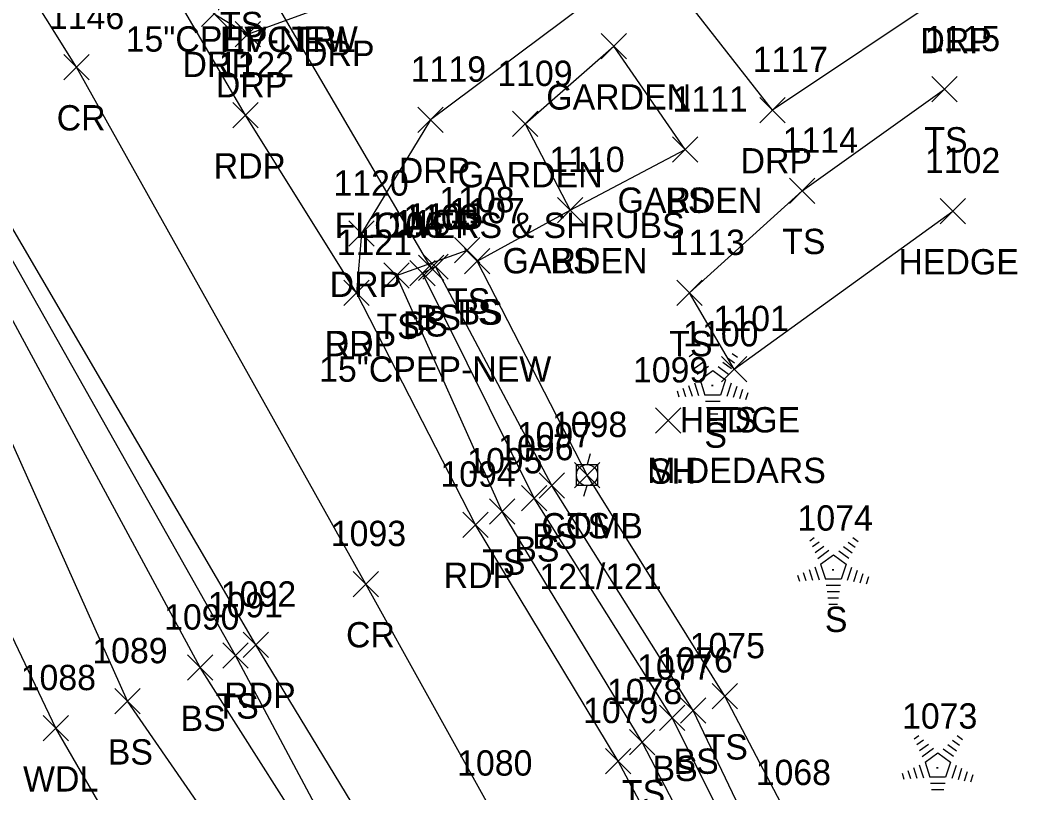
# Model space of a CAD drawing. Extents: x 1501299 to 1502485, y 381423 to 383765.
# Drawn here: x 1501851.9 to 1501931.5, y 382883 to 382944 of the extents above; entities that cross this region are included whole.
import ezdxf

# ---------------------------------------------------------------- set-up
doc = ezdxf.new("R2010")
doc.units = 0
for name, color, linetype in [('C_A', 7, 'Continuous'), ('D_A', 7, 'Continuous'), ('D_C', 7, 'Continuous'), ('D_I', 7, 'Continuous'), ('D_TIC', 7, 'Continuous'), ('DCP', 7, 'Continuous'), ('L_A', 7, 'Continuous'), ('L_C', 7, 'Continuous'), ('L_I', 7, 'Continuous'), ('L_TIC', 7, 'Continuous'), ('LAHR', 7, 'Continuous'), ('LAPB', 7, 'Continuous'), ('LAWA', 7, 'Continuous'), ('LELB', 7, 'Continuous'), ('LTC', 7, 'Continuous'), ('P_A', 7, 'Continuous'), ('P_I', 7, 'Continuous'), ('P_TIC', 7, 'Continuous'), ('PET', 7, 'Continuous'), ('PRC', 7, 'Continuous'), ('R_A', 7, 'Continuous'), ('R_I', 7, 'Continuous'), ('R_TIC', 7, 'Continuous'), ('RDP', 7, 'Continuous'), ('U_A', 7, 'Continuous'), ('U_C', 7, 'Continuous'), ('U_I', 7, 'Continuous'), ('UP', 7, 'Continuous')]:
    doc.layers.add(name, color=color, linetype=linetype)

msp = doc.modelspace()

# ---------------------------------------------------------------- linework, layer by layer
at = {"layer": 'D_TIC'}
for points in [[(1501883.401, 382923.481), (1501885.401, 382925.481)], [(1501885.401, 382923.481), (1501883.401, 382925.481)]]:
    msp.add_lwpolyline(points, dxfattribs=at)
at = {"layer": 'DCP'}
msp.add_lwpolyline([(1501884.401, 382924.481), (1501869.119, 382950.545)], dxfattribs=at)
at = {"layer": 'L_TIC'}
for points in [[(1501897.823, 382940.969), (1501899.823, 382942.969)], [(1501899.823, 382940.969), (1501897.823, 382942.969)], [(1501897.823, 382940.969), (1501899.823, 382942.969)], [(1501899.823, 382940.969), (1501897.823, 382942.969)], [(1501923.945, 382937.582), (1501925.945, 382939.582)], [(1501925.945, 382937.582), (1501923.945, 382939.582)], [(1501890.835, 382934.833), (1501892.835, 382936.833)], [(1501892.835, 382934.833), (1501890.835, 382936.833)], [(1501890.835, 382934.833), (1501892.835, 382936.833)], [(1501892.835, 382934.833), (1501890.835, 382936.833)], [(1501903.45, 382932.816), (1501905.45, 382934.816)], [(1501905.45, 382932.816), (1501903.45, 382934.816)], [(1501903.45, 382932.816), (1501905.45, 382934.816)], [(1501905.45, 382932.816), (1501903.45, 382934.816)], [(1501912.716, 382929.558), (1501914.716, 382931.558)], [(1501914.716, 382929.558), (1501912.716, 382931.558)], [(1501894.375, 382928.039), (1501896.375, 382930.039)], [(1501896.375, 382928.039), (1501894.375, 382930.039)], [(1501894.375, 382928.039), (1501896.375, 382930.039)], [(1501896.375, 382928.039), (1501894.375, 382930.039)], [(1501924.605, 382927.951), (1501926.605, 382929.951)], [(1501926.605, 382927.951), (1501924.605, 382929.951)], [(1501886.244, 382924.863), (1501888.244, 382926.863)], [(1501888.244, 382924.863), (1501886.244, 382926.863)], [(1501886.244, 382924.863), (1501888.244, 382926.863)], [(1501888.244, 382924.863), (1501886.244, 382926.863)], [(1501883.747, 382923.568), (1501885.747, 382925.568)], [(1501885.747, 382923.568), (1501883.747, 382925.568)], [(1501883.747, 382923.568), (1501885.747, 382925.568)], [(1501885.747, 382923.568), (1501883.747, 382925.568)], [(1501887.043, 382923.994), (1501889.043, 382925.994)], [(1501889.043, 382923.994), (1501887.043, 382925.994)], [(1501887.043, 382923.994), (1501889.043, 382925.994)], [(1501889.043, 382923.994), (1501887.043, 382925.994)], [(1501880.668, 382922.868), (1501882.668, 382924.868)], [(1501882.668, 382922.868), (1501880.668, 382924.868)], [(1501882.724, 382923.051), (1501884.724, 382925.051)], [(1501884.724, 382923.051), (1501882.724, 382925.051)], [(1501903.796, 382921.494), (1501905.796, 382923.494)], [(1501905.796, 382921.494), (1501903.796, 382923.494)], [(1501907.338, 382915.478), (1501909.338, 382917.478)], [(1501909.338, 382915.478), (1501907.338, 382917.478)], [(1501907.338, 382915.478), (1501909.338, 382917.478)], [(1501909.338, 382915.478), (1501907.338, 382917.478)], [(1501902.117, 382911.426), (1501904.117, 382913.426)], [(1501904.117, 382911.426), (1501902.117, 382913.426)], [(1501895.712, 382907.113), (1501897.712, 382909.113)], [(1501897.712, 382907.113), (1501895.712, 382909.113)], [(1501892.938, 382906.292), (1501894.938, 382908.292)], [(1501894.938, 382906.292), (1501892.938, 382908.292)], [(1501891.525, 382905.285), (1501893.525, 382907.285)], [(1501893.525, 382905.285), (1501891.525, 382907.285)], [(1501889.021, 382904.247), (1501891.021, 382906.247)], [(1501891.021, 382904.247), (1501889.021, 382906.247)], [(1501867.959, 382892.881), (1501869.959, 382894.881)], [(1501869.959, 382892.881), (1501867.959, 382894.881)], [(1501865.166, 382891.912), (1501867.166, 382893.912)], [(1501867.166, 382891.912), (1501865.166, 382893.912)], [(1501859.416, 382889.256), (1501861.416, 382891.256)], [(1501861.416, 382889.256), (1501859.416, 382891.256)], [(1501906.588, 382889.652), (1501908.588, 382891.652)], [(1501908.588, 382889.652), (1501906.588, 382891.652)], [(1501904.102, 382888.525), (1501906.102, 382890.525)], [(1501906.102, 382888.525), (1501904.102, 382890.525)], [(1501902.441, 382887.957), (1501904.441, 382889.957)], [(1501904.441, 382887.957), (1501902.441, 382889.957)], [(1501853.75, 382887.13), (1501855.75, 382889.13)], [(1501855.75, 382887.13), (1501853.75, 382889.13)], [(1501900.055, 382886.028), (1501902.055, 382888.028)], [(1501902.055, 382886.028), (1501900.055, 382888.028)]]:
    msp.add_lwpolyline(points, dxfattribs=at)
at = {"layer": 'LAHR'}
msp.add_lwpolyline([(1501908.338, 382916.478), (1501925.605, 382928.951)], dxfattribs=at)
at = {"layer": 'LAPB'}
for points in [[(1501891.835, 382935.833), (1501895.375, 382929.039), (1501904.45, 382933.816), (1501898.823, 382941.969)], [(1501891.835, 382935.833), (1501898.823, 382941.969)]]:
    msp.add_lwpolyline(points, dxfattribs=at)
at = {"layer": 'LAWA'}
msp.add_lwpolyline([(1501942.677, 382714.841), (1501935.183, 382744.721), (1501913.337, 382785.2), (1501893.395, 382826.433), (1501865.291, 382869.925), (1501854.75, 382888.13), (1501835.928, 382927.55), (1501822.234, 382953.468), (1501796.607, 382993.044), (1501779.613, 383024.31), (1501754.165, 383064.049), (1501733.525, 383095.142)], dxfattribs=at)
at = {"layer": 'LELB'}
for points in [[(1501947.071, 382716.202), (1501936.789, 382745.616), (1501921.74, 382787.499), (1501900.168, 382829.778), (1501877.018, 382875.801), (1501866.166, 382892.912), (1501844.624, 382932.733), (1501828.058, 382959.038), (1501805.265, 382995.601), (1501783.687, 383028.162), (1501760.133, 383067.523), (1501734.806, 383103.876), (1501716.067, 383128.727), (1501702.976, 383136.285), (1501694.191, 383132.723)], [(1501947.958, 382716.119), (1501939.996, 382745.704), (1501923.414, 382788.324), (1501902.81, 382830.435), (1501868.959, 382893.881), (1501846.402, 382933.734), (1501830.033, 382960.147), (1501806.634, 382996.692), (1501785.685, 383029.202), (1501761.094, 383068.04), (1501736.237, 383105.316), (1501718.865, 383131.579)], [(1501945.344, 382716.136), (1501936.673, 382745.194), (1501918.388, 382786.659), (1501897.882, 382827.989), (1501871.615, 382874.073), (1501860.416, 382890.256), (1501841.87, 382931.652), (1501826.472, 382956.951), (1501803.66, 382993.76), (1501782.057, 383026.726), (1501758.572, 383066.643), (1501733.616, 383102.86), (1501712.412, 383124.491), (1501694.918, 383122.167), (1501687.272, 383121.659)], [(1501908.338, 382916.478), (1501904.796, 382922.494), (1501913.716, 382930.558), (1501924.945, 382938.582)], [(1501888.043, 382924.994), (1501895.375, 382929.039)], [(1501911.592, 382870.97), (1501909.37, 382871.043), (1501901.055, 382887.028), (1501890.021, 382905.247), (1501881.668, 382923.868), (1501887.244, 382925.863)], [(1501913.743, 382873.819), (1501912.85, 382880.639), (1501907.588, 382890.652), (1501896.712, 382908.113), (1501888.043, 382924.994), (1501887.244, 382925.863)], [(1501911.192, 382873.468), (1501903.441, 382888.957), (1501892.525, 382906.285), (1501883.724, 382924.051), (1501884.747, 382924.568)], [(1501911.192, 382873.468), (1501911.937, 382871.769), (1501912.981, 382872.458), (1501912.438, 382874.164), (1501905.102, 382889.525), (1501893.938, 382907.292), (1501884.747, 382924.568)]]:
    msp.add_lwpolyline(points, dxfattribs=at)
at = {"layer": 'LTC'}
for p, q in [((1501904.789, 382917.479), (1501905.143, 382917.736)), ((1501904.998, 382917.014), (1501905.528, 382917.398)), ((1501908.187, 382917.719), (1501908.606, 382917.415)), ((1501905.208, 382916.548), (1501905.912, 382917.059)), ((1501905.418, 382916.082), (1501906.296, 382916.72)), ((1501907.074, 382916.674), (1501907.883, 382916.086)), ((1501907.445, 382917.023), (1501908.124, 382916.529)), ((1501907.816, 382917.371), (1501908.366, 382916.972)), ((1501905.642, 382915.627), (1501906.654, 382916.361)), ((1501906.654, 382916.361), (1501907.651, 382915.636)), ((1501904.732, 382915.191), (1501905.003, 382914.356)), ((1501905.188, 382915.408), (1501905.518, 382914.389)), ((1501905.642, 382915.627), (1501906.029, 382914.434)), ((1501907.651, 382915.636), (1501907.26, 382914.434)), ((1501908.088, 382915.366), (1501907.751, 382914.326)), ((1501908.533, 382915.115), (1501908.246, 382914.231)), ((1501903.821, 382914.758), (1501903.973, 382914.29)), ((1501904.277, 382914.975), (1501904.488, 382914.323)), ((1501907.26, 382914.434), (1501906.029, 382914.434)), ((1501908.978, 382914.865), (1501908.741, 382914.136)), ((1501909.422, 382914.615), (1501909.235, 382914.041)), ((1501907.221, 382913.934), (1501906.077, 382913.934)), ((1501907.138, 382913.434), (1501906.149, 382913.434)), ((1501907.054, 382912.934), (1501906.222, 382912.934)), ((1501906.97, 382912.434), (1501906.295, 382912.434)), ((1501914.305, 382902.933), (1501914.659, 382903.191)), ((1501917.703, 382903.174), (1501918.122, 382902.869)), ((1501914.514, 382902.468), (1501915.044, 382902.852)), ((1501914.724, 382902.002), (1501915.428, 382902.513)), ((1501916.961, 382902.477), (1501917.64, 382901.983)), ((1501917.332, 382902.825), (1501917.882, 382902.426)), ((1501914.934, 382901.536), (1501915.812, 382902.174)), ((1501915.158, 382901.081), (1501916.17, 382901.816)), ((1501916.17, 382901.816), (1501917.167, 382901.091)), ((1501916.59, 382902.129), (1501917.399, 382901.54)), ((1501914.704, 382900.862), (1501915.034, 382899.843)), ((1501915.158, 382901.081), (1501915.545, 382899.888)), ((1501917.167, 382901.091), (1501916.776, 382899.888)), ((1501917.604, 382900.82), (1501917.267, 382899.78)), ((1501913.337, 382900.212), (1501913.489, 382899.744)), ((1501913.793, 382900.429), (1501914.004, 382899.777)), ((1501914.248, 382900.646), (1501914.519, 382899.81)), ((1501916.776, 382899.888), (1501915.545, 382899.888)), ((1501918.049, 382900.569), (1501917.762, 382899.685)), ((1501918.494, 382900.319), (1501918.257, 382899.59)), ((1501918.938, 382900.069), (1501918.751, 382899.495)), ((1501916.737, 382899.388), (1501915.593, 382899.388)), ((1501916.654, 382898.888), (1501915.665, 382898.888)), ((1501916.57, 382898.388), (1501915.738, 382898.388)), ((1501916.486, 382897.888), (1501915.811, 382897.888)), ((1501922.557, 382887.3), (1501922.911, 382887.558)), ((1501922.766, 382886.835), (1501923.295, 382887.219)), ((1501925.584, 382887.192), (1501926.133, 382886.793)), ((1501925.955, 382887.54), (1501926.374, 382887.236)), ((1501922.976, 382886.369), (1501923.679, 382886.88)), ((1501923.185, 382885.903), (1501924.064, 382886.541)), ((1501924.842, 382886.495), (1501925.651, 382885.907)), ((1501925.213, 382886.844), (1501925.892, 382886.35)), ((1501923.41, 382885.448), (1501924.422, 382886.183)), ((1501924.422, 382886.183), (1501925.419, 382885.458)), ((1501922.044, 382884.796), (1501922.256, 382884.144)), ((1501922.5, 382885.013), (1501922.771, 382884.177)), ((1501922.955, 382885.229), (1501923.286, 382884.21)), ((1501923.41, 382885.448), (1501923.797, 382884.255)), ((1501925.419, 382885.458), (1501925.027, 382884.255)), ((1501925.856, 382885.187), (1501925.518, 382884.147)), ((1501926.301, 382884.936), (1501926.013, 382884.052)), ((1501921.589, 382884.579), (1501921.741, 382884.111)), ((1501925.027, 382884.255), (1501923.797, 382884.255)), ((1501926.745, 382884.686), (1501926.508, 382883.957)), ((1501927.189, 382884.436), (1501927.003, 382883.862)), ((1501924.989, 382883.755), (1501923.844, 382883.755)), ((1501924.905, 382883.255), (1501923.917, 382883.255))]:
    msp.add_line(p, q, dxfattribs=at)
at = {"layer": 'P_TIC'}
for points in [[(1501855.391, 382939.32), (1501857.391, 382941.32)], [(1501857.391, 382939.32), (1501855.391, 382941.32)], [(1501868.738, 382935.529), (1501870.738, 382937.529)], [(1501870.738, 382935.529), (1501868.738, 382937.529)], [(1501877.505, 382921.493), (1501879.505, 382923.493)], [(1501879.505, 382921.493), (1501877.505, 382923.493)], [(1501886.899, 382903.195), (1501888.899, 382905.195)], [(1501888.899, 382903.195), (1501886.899, 382905.195)], [(1501878.244, 382898.507), (1501880.244, 382900.507)], [(1501880.244, 382898.507), (1501878.244, 382900.507)], [(1501869.565, 382893.723), (1501871.565, 382895.723)], [(1501871.565, 382893.723), (1501869.565, 382895.723)], [(1501898.175, 382884.527), (1501900.175, 382886.527)], [(1501900.175, 382884.527), (1501898.175, 382886.527)]]:
    msp.add_lwpolyline(points, dxfattribs=at)
at = {"layer": 'PET'}
for points in [[(1501949.648, 382716.507), (1501941.04, 382745.977), (1501925.012, 382788.592), (1501904.253, 382831.621), (1501880.763, 382877.887), (1501870.565, 382894.723), (1501847.406, 382934.273), (1501830.938, 382961.01), (1501807.981, 382997.987), (1501787.075, 383029.946), (1501762.257, 383068.782), (1501737.378, 383106.292), (1501722.895, 383129.668), (1501696.699, 383166.339)], [(1501971.372, 382720.654), (1501961.032, 382754.708), (1501942.926, 382798.84), (1501930.998, 382825.078), (1501924.576, 382839.599), (1501916.528, 382851.603), (1501908.311, 382868.386), (1501899.175, 382885.527), (1501887.899, 382904.195), (1501878.505, 382922.493), (1501869.738, 382936.529), (1501858.065, 382956.489), (1501847.469, 382974.349), (1501824.868, 383010.254), (1501802.294, 383043.804), (1501787.994, 383066.094), (1501768.484, 383096.751)]]:
    msp.add_lwpolyline(points, dxfattribs=at)
at = {"layer": 'PRC'}
msp.add_lwpolyline([(1501960.612, 382718.648), (1501950.96, 382750.482), (1501934.965, 382791.852), (1501913.074, 382836.935), (1501889.309, 382881.383), (1501879.244, 382899.507), (1501856.391, 382940.32), (1501839.674, 382966.998), (1501816.055, 383004.313), (1501794.783, 383036.247), (1501769.812, 383075.158), (1501745.791, 383111.558), (1501729.435, 383136.001), (1501711.236, 383163.535), (1501694.816, 383188.199), (1501683.547, 383204.004), (1501664.644, 383231.239), (1501639.517, 383268.342), (1501626.393, 383287.881)], dxfattribs=at)
at = {"layer": 'R_TIC'}
for points in [[(1501866.271, 382943.539), (1501868.271, 382945.539)], [(1501868.271, 382943.539), (1501866.271, 382945.539)], [(1501868.909, 382941.926), (1501870.909, 382943.926)], [(1501870.909, 382941.926), (1501868.909, 382943.926)], [(1501910.348, 382935.93), (1501912.348, 382937.93)], [(1501912.348, 382935.93), (1501910.348, 382937.93)], [(1501883.354, 382935.169), (1501885.354, 382937.169)], [(1501885.354, 382935.169), (1501883.354, 382937.169)], [(1501877.896, 382926.174), (1501879.896, 382928.174)], [(1501879.896, 382926.174), (1501877.896, 382928.174)], [(1501877.505, 382921.493), (1501879.505, 382923.493)], [(1501879.505, 382921.493), (1501877.505, 382923.493)]]:
    msp.add_lwpolyline(points, dxfattribs=at)
at = {"layer": 'RDP'}
for points in [[(1501858.065, 382956.489), (1501858.951, 382957.67), (1501867.271, 382944.539), (1501869.909, 382942.926), (1501876.795, 382945.413), (1501892.372, 382955.336), (1501908.287, 382967.125)], [(1501925.551, 382946.422), (1501911.348, 382936.93), (1501901.78, 382949.177), (1501884.354, 382936.169), (1501878.896, 382927.174), (1501878.505, 382922.493)]]:
    msp.add_lwpolyline(points, dxfattribs=at)
at = {"layer": 'UP'}
for p, q in [((1501896.962, 382909.78), (1501896.712, 382908.946)), ((1501895.878, 382907.28), (1501895.878, 382908.946)), ((1501895.878, 382908.946), (1501897.545, 382908.946)), ((1501897.545, 382908.946), (1501897.545, 382907.28)), ((1501896.712, 382908.113), (1501896.712, 382908.113)), ((1501897.545, 382907.28), (1501895.878, 382907.28)), ((1501896.462, 382906.447), (1501896.712, 382907.28))]:
    msp.add_line(p, q, dxfattribs=at)
msp.add_circle((1501896.712, 382908.113), 0.833, dxfattribs=at)

# ---------------------------------------------------------------- texts
at = {"layer": 'C_A'}
msp.add_text('HVCTRL', height=2, dxfattribs=at).set_placement((1501867.716, 382941.512))
at = {"layer": 'D_A'}
msp.add_text('P', height=2, dxfattribs=at).set_placement((1501883.779, 382919.481))
at = {"layer": 'D_C'}
for p in [(1501860.269, 382941.545), (1501875.551, 382915.481)]:
    msp.add_text('15"CPEP-NEW', height=2, dxfattribs=at).set_placement(p)
at = {"layer": 'D_I'}
msp.add_text('1103', height=2, dxfattribs=at).set_placement((1501882.197, 382927.481))
at = {"layer": 'L_A'}
for s, p in [('TS', (1501867.724, 382942.686)), ('GARDEN', (1501893.492, 382936.969)), ('GARDEN', (1501893.492, 382936.969)), ('TS', (1501923.354, 382933.582)), ('GARDEN', (1501886.504, 382930.833)), ('GARDEN', (1501886.504, 382930.833)), ('GARDEN', (1501899.119, 382928.816)), ('BS', (1501902.891, 382928.816)), ('TS', (1501912.126, 382925.558)), ('GARDEN', (1501890.044, 382924.039)), ('BS', (1501893.816, 382924.039)), ('HEDGE', (1501921.305, 382923.951)), ('TS', (1501885.653, 382920.863)), ('TS', (1501885.653, 382920.863)), ('BS', (1501883.188, 382919.568)), ('BS', (1501883.188, 382919.568)), ('TS', (1501886.453, 382919.994)), ('BS', (1501886.484, 382919.994)), ('TS', (1501880.077, 382918.868)), ('BS', (1501882.165, 382919.051)), ('TS', (1501903.205, 382917.494)), ('HEDGE', (1501904.039, 382911.478)), ('TS', (1501906.748, 382911.478)), ('S', (1501905.98, 382910.271)), ('SH', (1501901.605, 382907.426)), ('TS', (1501895.121, 382903.113)), ('BS', (1501892.378, 382902.292)), ('BS', (1501890.966, 382901.285)), ('TS', (1501888.431, 382900.247)), ('S', (1501915.496, 382895.725)), ('TS', (1501867.369, 382888.881)), ('BS', (1501864.607, 382887.912)), ('BS', (1501858.857, 382885.256)), ('TS', (1501905.998, 382885.652)), ('BS', (1501903.543, 382884.525)), ('BS', (1501901.882, 382883.957)), ('WDL', (1501852.167, 382883.13)), ('TS', (1501899.464, 382882.028))]:
    msp.add_text(s, height=2, dxfattribs=at).set_placement(p)
at = {"layer": 'L_C'}
for s, p in [('FLOWERS & SHRUBS', (1501876.78, 382926.833)), ('FLOWERS & SHRUBS', (1501876.78, 382926.833)), ('M.DEDARS', (1501901.457, 382907.478))]:
    msp.add_text(s, height=2, dxfattribs=at).set_placement(p)
at = {"layer": 'L_I'}
for s, p in [('1115', (1501923.386, 382941.582)), ('1109', (1501889.623, 382938.833)), ('1109', (1501889.623, 382938.833)), ('1111', (1501903.458, 382936.816)), ('1111', (1501903.458, 382936.816)), ('1114', (1501912.157, 382933.558)), ('1110', (1501893.73, 382932.039)), ('1110', (1501893.73, 382932.039)), ('1102', (1501923.4, 382931.951)), ('1108', (1501885.039, 382928.863)), ('1108', (1501885.039, 382928.863)), ('1105', (1501882.543, 382927.568)), ('1105', (1501882.543, 382927.568)), ('1107', (1501885.839, 382927.994)), ('1107', (1501885.839, 382927.994)), ('1106', (1501879.408, 382926.868)), ('1104', (1501881.52, 382927.051)), ('1113', (1501903.237, 382925.494)), ('1101', (1501906.701, 382919.478)), ('1101', (1501906.701, 382919.478)), ('1100', (1501904.303, 382918.271)), ('1099', (1501900.338, 382915.426)), ('1098', (1501893.94, 382911.113)), ('1097', (1501891.166, 382910.292)), ('1096', (1501889.698, 382909.285)), ('1095', (1501887.25, 382908.247)), ('1074', (1501913.338, 382903.725)), ('1091', (1501866.755, 382896.881)), ('1090', (1501863.308, 382895.912)), ('1089', (1501857.637, 382893.256)), ('1075', (1501904.817, 382893.652)), ('1076', (1501902.276, 382892.525)), ('1077', (1501900.67, 382891.957)), ('1088', (1501851.978, 382891.13)), ('1078', (1501898.283, 382890.028)), ('1073', (1501921.59, 382888.092)), ('1068', (1501910.031, 382883.639))]:
    msp.add_text(s, height=2, dxfattribs=at).set_placement(p)
at = {"layer": 'LTC'}
for p in [(1501906.536, 382915.375), (1501916.052, 382900.829), (1501924.304, 382885.196)]:
    msp.add_text('.', height=1.037, rotation=270, dxfattribs=at).set_placement(p)
at = {"layer": 'P_A'}
for s, p in [('CR', (1501854.824, 382935.32)), ('RDP', (1501867.226, 382931.529)), ('RDP', (1501875.993, 382917.493)), ('RDP', (1501885.388, 382899.195)), ('CR', (1501877.677, 382894.507)), ('RDP', (1501868.053, 382889.723))]:
    msp.add_text(s, height=2, dxfattribs=at).set_placement(p)
at = {"layer": 'P_I'}
for s, p in [('1146', (1501854.21, 382943.32)), ('1122', (1501867.612, 382939.529)), ('1121', (1501876.946, 382925.493)), ('1094', (1501885.128, 382907.195)), ('1093', (1501876.473, 382902.507)), ('1092', (1501867.793, 382897.723)), ('1079', (1501896.396, 382888.527)), ('1080', (1501886.451, 382884.383))]:
    msp.add_text(s, height=2, dxfattribs=at).set_placement(p)
at = {"layer": 'R_A'}
for p in [(1501923.039, 382941.422), (1501874.283, 382940.413), (1501864.76, 382939.539), (1501867.397, 382937.926), (1501908.836, 382931.93), (1501881.842, 382931.169), (1501876.384, 382922.174), (1501875.993, 382917.493)]:
    msp.add_text('DRP', height=2, dxfattribs=at).set_placement(p)
at = {"layer": 'R_I'}
for s, p in [('1117', (1501909.789, 382939.93)), ('1119', (1501882.787, 382939.169)), ('1120', (1501876.683, 382930.174)), ('1121', (1501876.946, 382925.493))]:
    msp.add_text(s, height=2, dxfattribs=at).set_placement(p)
at = {"layer": 'U_A'}
msp.add_text('COMB', height=2, dxfattribs=at).set_placement((1501893.098, 382903.113))
at = {"layer": 'U_C'}
msp.add_text('121/121', height=2, dxfattribs=at).set_placement((1501892.948, 382899.113))
at = {"layer": 'U_I'}
msp.add_text('1098', height=2, dxfattribs=at).set_placement((1501893.94, 382911.113))

doc.saveas('drawing.dxf')
